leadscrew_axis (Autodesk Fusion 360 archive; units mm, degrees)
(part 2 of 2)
chamfer "Chamfer2" distance 3
fillet "Fillet3" radius 3
named bodies: "leadscrew_motor_mount"

design "HW_M3x16-SHCS"
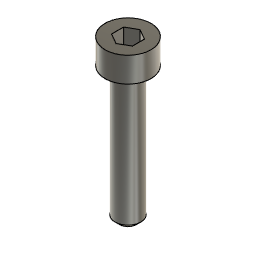
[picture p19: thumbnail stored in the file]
sketch "Sketch1" plane through (0, 0, 0) normal (0, 1, 0) x axis (1, 0, 0)
  line L1 (0, 16) -> (0, -3)
  line L2 (1.05, 16) -> (0, 16)
  line L3 (1.55, 15.5) -> (1.05, 16)
  line L4 (1.55, 0) -> (1.55, 15.5)
  line L5 (2.75, 0) -> (1.55, 0)
  line L6 (2.75, -3) -> (2.75, 0)
  line L7 (0, -3) -> (2.75, -3)
  point P1 (0, 0)
  point P4 (1.05, 16)
  point P5 (1.55, 15.5)
  point P3 (0, 16)
  point P7 (2.75, 0)
  point P8 (2.75, -3)
  point P2 (0, -3)
  vertical L1
  perpendicular L1 L2
  perpendicular L2 L4
  perpendicular L4 L5
  perpendicular L5 L6
  horizontal L7
  coincident P1 L1
  coincident P1 L5
  dimension "d1" distance P1 L2 = 16
  dimension "d2" angle L2 L3 = 45
  dimension "d3" distance P4 P5 = 0.5
  dimension "d4" distance P3 L4 = 1.55 (= "( 3.1 / 2 ) * 1 mm")
  dimension "d5" distance P7 P8 = 3
  dimension "d6" distance P2 P8 = 2.75 (= "( 5.5 / 2 ) * 1 mm")
revolve "Revolve1" sketch "Sketch1" AlongAngle 360
sketch "Sketch2" plane through (0, 0, 3) normal (0, 0, 1) x axis (-1, 0, 0)
  line L1 (0, -1.4434) -> (-1.25, -0.7217)
  line L2 (1.25, -0.7217) -> (0, -1.4434)
  line L3 (1.25, 0.7217) -> (1.25, -0.7217)
  line L4 (0, 1.4434) -> (1.25, 0.7217)
  line L5 (-1.25, 0.7217) -> (0, 1.4434)
  line L6 (-1.25, -0.7217) -> (-1.25, 0.7217)
  circle C1 centre (0, 0) radius 2.75
  point P1 (0, 0)
  point P9 (0, 0)
  point P5 (1.25, -0.7217)
  coincident P1 P9
  vertical L6
  dimension "d8" distance P5 L6 = 2.5
extrude "Extrude1" cut sketch "Sketch2" profile of L1 L2 L3 L4 L5 L6 against normal blind 2

design "leadscrew_clip"
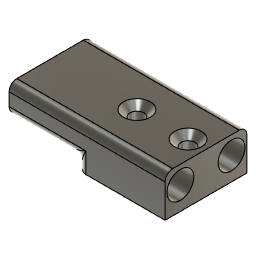
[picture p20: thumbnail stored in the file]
sketch "Sketch1" plane through (0, 0, 0) normal (0, 0, 1) x axis (1, 0, 0)
  line L1 (0, 32) -> (0, 0)
  line L2 (61, 32) -> (0, 32)
  line L3 (61, 0) -> (61, 32)
  line L4 (0, 0) -> (61, 0)
  line L5 (1, 32) -> (1, 0)
  line L6 (21, 32) -> (21, 0)
  line L7 (27, 0) -> (27, 32)
  line L8 (44, 0) -> (44, 32)
  line L9 (54, 16) -> (34, 16)
  circle C1 centre (34, 16) radius 2.75
  circle C2 centre (54, 16) radius 2.75
  point P1 (0, 0)
  point P2 (0, 0)
  point P6 (0, 0)
  point P7 (1, 0)
  point P8 (1, 32)
  point P9 (21, 0)
  point P10 (21, 32)
  point P11 (27, 32)
  point P12 (27, 0)
  point P13 (44, 32)
  point P14 (44, 0)
  point P15 (34, 16)
  point P17 (34, 16)
  point P16 (54, 16)
  point P18 (54, 16)
  point P19 (44, 16)
  point P3 (0, 32)
  point P4 (61, 32)
  coincident P1 P2
  vertical L1
  perpendicular L1 L2
  perpendicular L2 L3
  perpendicular L3 L4
  coincident P1 P6
  coincident L4 P7
  perpendicular L4 L5
  coincident L2 P8
  coincident L4 P9
  coincident L2 P10
  perpendicular L2 L6
  coincident L2 P11
  perpendicular L4 L7
  coincident L4 P12
  coincident L2 P13
  coincident L4 P14
  perpendicular L4 L8
  coincident P15 P17
  coincident P16 P18
  horizontal L9
  midpoint L9 P19
  midpoint L8 P19
  equal C1 C2
  dimension "d1" distance P2 P3 = 32
  dimension "d4" distance P1 L5 = 1
  dimension "d5" distance P8 P10 = 20
  dimension "d36" distance P10 L7 = 6
  dimension "d73" distance P1 P14 = 44
  dimension "d74" distance P4 P11 = 34
  dimension "d75" distance P11 P13 = 17 (= "d74 / 2")
  dimension "d76" diameter C1 = 5.5
  dimension "d77" distance P17 P18 = 20
  dimension "d31" Side1Offset = 0
  dimension "d32" TaperAngle = 0
  dimension "d40" distance = 10
  dimension "d41" distance = 5
  dimension "d42" diameter = 5.5
  dimension "d49" diameter = 10
  dimension "d50" diameter = 5.5
  dimension "d51" diameter = 4.4
  dimension "d52" distance = 3
  dimension "d54" distance = 6
  dimension "d55" distance = 6
  dimension "d61" diameter = 10
  dimension "d72" mirrorStitchTolerance = 0.1
extrude "Extrude1" new body sketch "Sketch1" profile of L1 L2 L4 L7 blind 11 from offset 1 bodies "leadscrew_clip"
extrude "Extrude11" sketch "Sketch1" profile of L2 L3 L4 L7 C1 C2 blind -5
extrude "Extrude12" cut sketch "Sketch1" profile of C1 C2 no distance stored
sketch "Sketch4" plane through (0, 0, 0) normal (-1, 0, 0) x axis (0, -1, 0)
  line L1 (0, 1) -> (-32, 1)
  line L2 (0, 12) -> (0, 1)
  line L3 (-32, 12) -> (0, 12)
  line L4 (-32, 1) -> (-32, 12)
  line L5 (-6, 5) -> (-26, 5)
  circle C1 centre (-26, 5) radius 2.875
  circle C2 centre (-6, 5) radius 2.875
  circle C3 centre (-6, 5) radius 5.25
  circle C4 centre (-26, 5) radius 5.25
  point P9 (-6, 5)
  point P10 (-6, 5)
  point P6 (-26, 5)
  point P8 (-26, 5)
  point P7 (-6, 5)
  point P11 (-26, 5)
  horizontal L5
  coincident P9 P10
  concentric C1 C4
  equal C1 C2
  equal C3 C4
  coincident P6 P8
  coincident P7 P10
  dimension "d82" distance P6 P7 = 20
  dimension "d83" diameter C1 = 5.75
  dimension "d84" diameter C4 = 10.5
  dimension "d85" distance L1 L5 = 4
  dimension "d86" distance L4 P11 = 6
extrude "Extrude13" cut sketch "Sketch4" profile of C1 C2 to an object
extrude "Extrude14" cut sketch "Sketch4" profile of L1 C1 C2 C3 C4 to an object from offset -30
chamfer "Chamfer3" distance 2.375
fillet "Fillet4" radius 3
fillet "Fillet5" radius 3
fillet "Fillet6" radius 3
chamfer "Chamfer4" distance 2.5
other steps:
step "Extrude5" ProfileOffset 0 Side1Offset 0 TaperAngle 0
step "Extrude6" ProfileOffset 0 Side1Offset 0 TaperAngle 0
step "Extrude8" Side1Offset 0 TaperAngle 0
step "Extrude9" AlongDistance -5 TaperAngle 0
step "Chamfer1" Distance 2.5
step "Extrude10" Side1Offset 0 TaperAngle 0
step "Chamfer2" Distance 2.5
step "Fillet1" Radius 6
step "Fillet2" Radius 1
step "Fillet3" Radius 3
named bodies: "leadscrew_clip"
